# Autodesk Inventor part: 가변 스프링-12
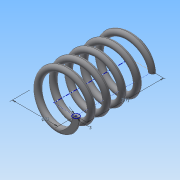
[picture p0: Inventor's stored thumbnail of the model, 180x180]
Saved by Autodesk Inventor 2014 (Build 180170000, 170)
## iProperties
Created: 2015-09
Part Number: 가변 스프링-12
Material: 강철, 탄소
Document SubType Name: Modeling
Designer: study
Density: 7.87 g/cm^3
Appearance: 반연마
Mass: 18.8856 g
Surface Area: 32.5491 cm^2
Volume: 2.3997 cm^3
Author: study
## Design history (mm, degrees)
sketch "스케치1"
  geometry: L1 (0, 0)-(11, 0); L2 (11, 0)-(11, 36.411); L3 (11, 36.411)-(0, 36.411); L4 (0, 36.411)-(0, 0); C1 r 1.5 at (11, 0)
  constraints: 8 end point, 2 parallel, 1 centre point, 1 coincident, 1 horizontal, 1 perpendicular
  dimensions: "d0" = 36.4112 distance of L1.end L2.end (derived); "d1" = 22 diameter of L1.end L4; "d2" = 3 diameter of C1
feature "코일1" sketch "스케치1" pitch "d3" = 10; turns "d5" = 5; dims "d4" = 36.4112 (= d0), "d6" = 0, angle "d7" = 90 deg, angle "d8" = 90 deg, "d9" = 0, "d10" = 0
node "작업 평면1"
sketch "스케치2"
  geometry: L1 (-12.5, 0)-(-9.5, 0) reference; 1 further point
  constraints: 1 horizontal alignment
extrude "돌출1" cut sketch "스케치2" stored distance "d12" = 10; taper "d13" = 0 deg
node "작업 평면2"
sketch "스케치3"
  geometry: L1 (-9.5, 0)-(-12.5, 0) reference; 1 further point
  constraints: 1 horizontal alignment
extrude "돌출2" cut sketch "스케치3" stored distance "d15" = 10; taper "d16" = 0 deg
node "솔리드1"
node "절단 모서리 투영1"
node "절단 모서리 투영2"
other parameters: "d11" = 0, "d14" = 36.4112 (= d0)
